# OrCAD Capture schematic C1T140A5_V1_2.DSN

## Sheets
1 00_Log: rev: <V1.2>; note: C1T140A5
2 01_CPU: size A4; title: Telink-Semi; rev: V1.2
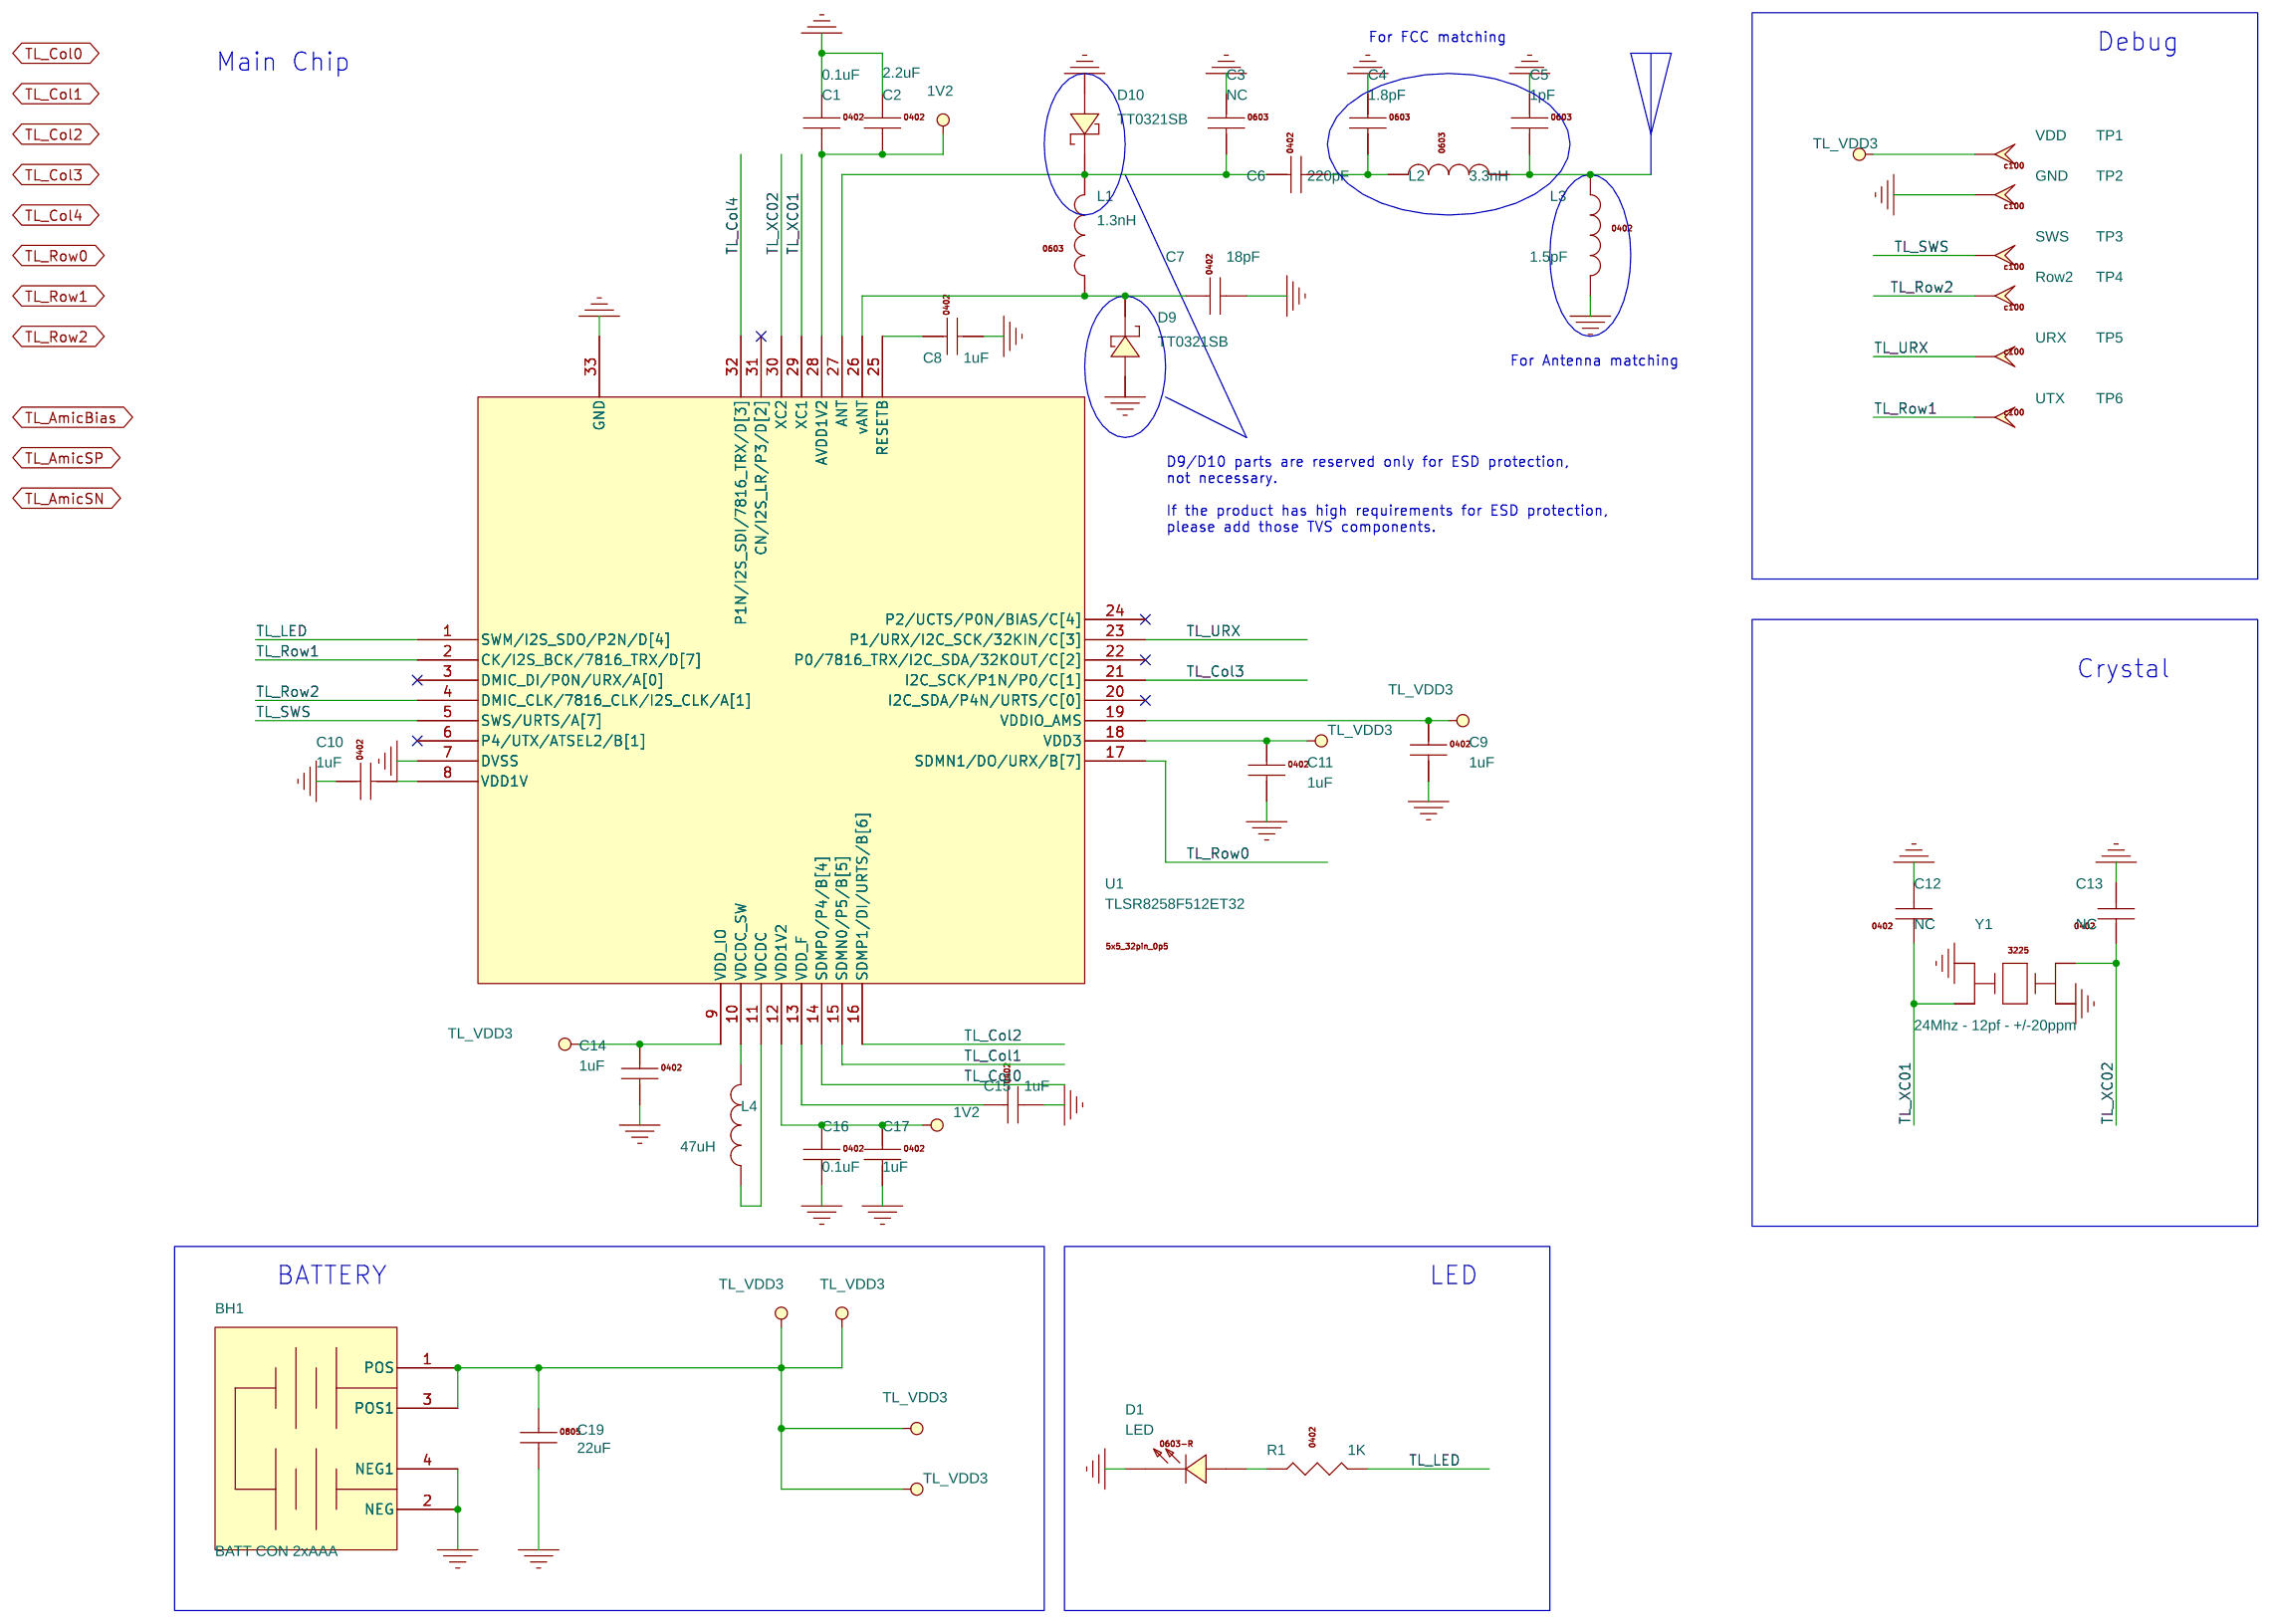
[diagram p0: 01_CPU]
3 02_KEY: size A
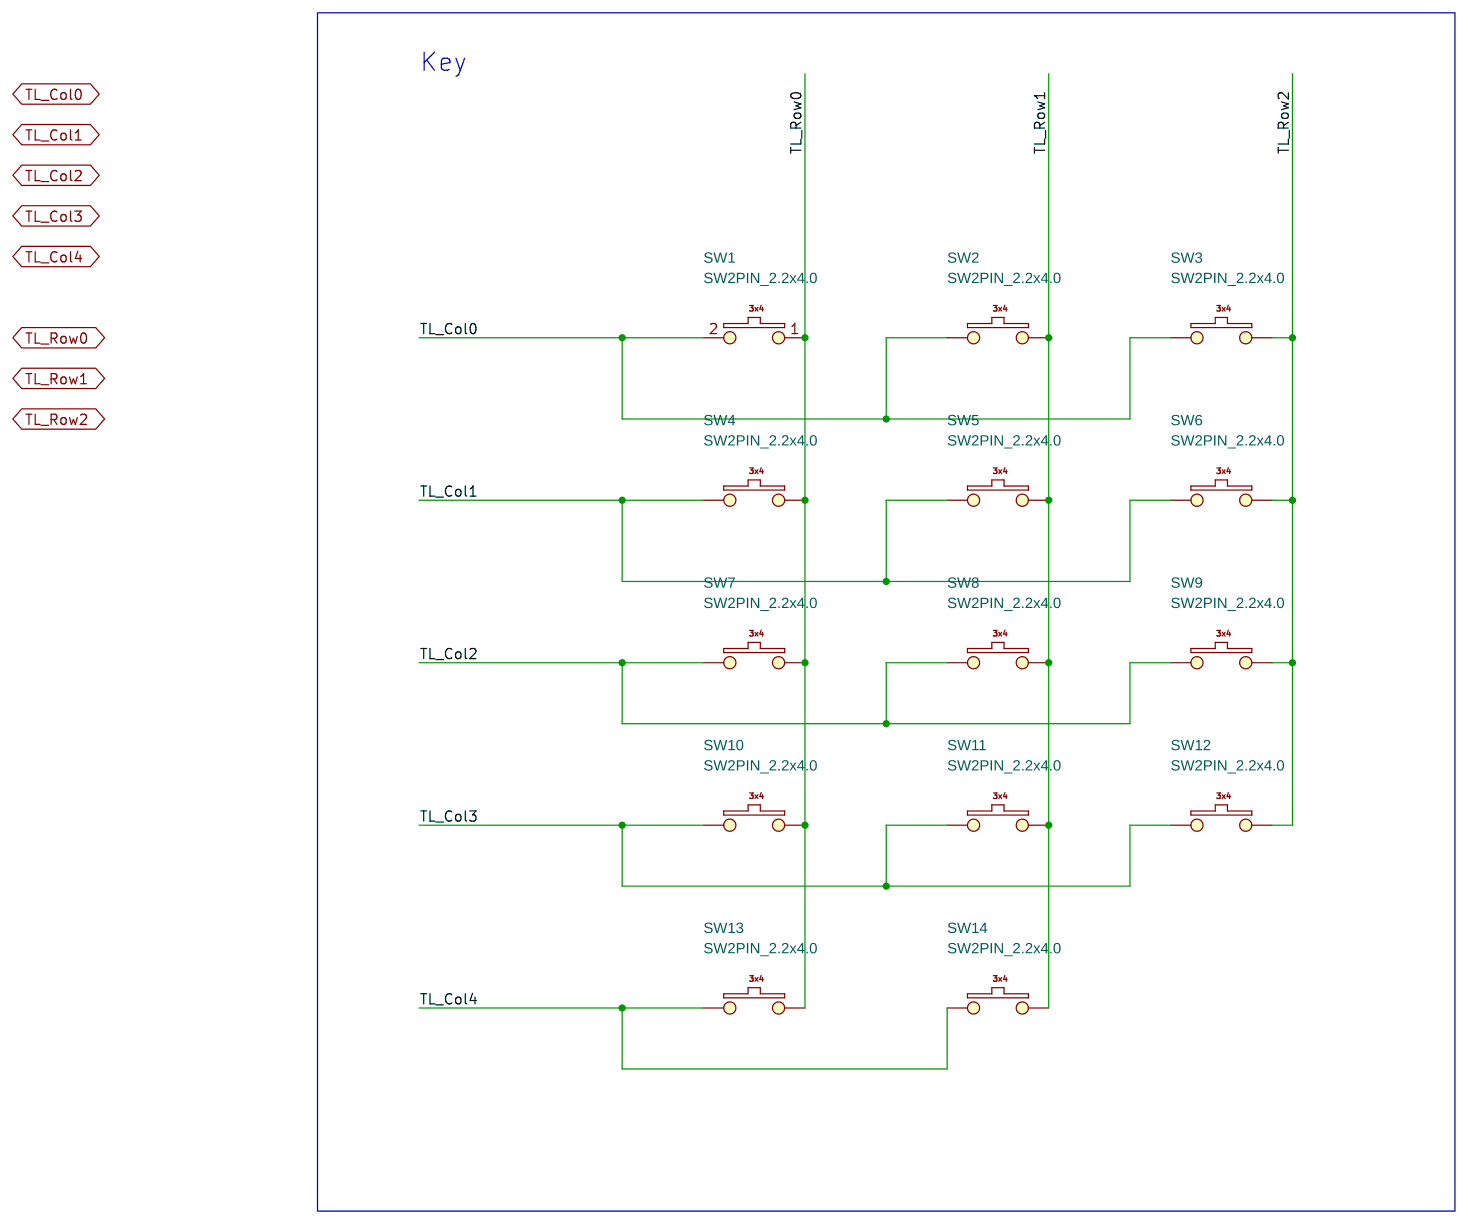
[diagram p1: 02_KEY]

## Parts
sheet 01_CPU
BH1  BATT CON 2xAAA  [bat]
C1  0.1uF  [0402]
C2  2.2uF  [0402]
C3  NC  [0402]
C4  1.8pF  [0402]
C5  1pF  [0402]
C6  220pF  [0402]
C7  18pF  [0402]
C8  1uF  [0402]
C9  1uF  [0402]
C10  1uF  [0402]
C11  1uF  [0402]
C12  NC  [0402]
C13  NC  [0402]
C14  1uF  [0402]
C15  1uF  [0402]
C16  0.1uF  [0402]
C17  1uF  [0402]
C19  22uF  [0805C]
D1  LED  [0603-LED]
D9  TT0321SB  [SOD-123]
D10  TT0321SB  [SOD-123]
L1  1.3nH  [0402]
L2  3.3nH  [0402]
L3  1.5pF  [0402]
L4  47uH  [0805L]
R1  1K  [0402]
TP1  VDD  [tp100]
TP2  GND  [tp100]
TP3  SWS  [tp100]
TP4  Row2  [tp100]
TP5  URX  [tp100]
TP6  UTX  [tp100]
U1  TLSR8258F512ET32  [qfn_5x5_32pin_0p5_2p50x2p50]
Y1  24Mhz - 12pf - +/-20ppm  [osccc250x320x110]
sheet 02_KEY
SW1  SW2PIN_2.2x4.0  [sw_out6_in3_new]
SW2  SW2PIN_2.2x4.0  [sw_out6_in3_new]
SW3  SW2PIN_2.2x4.0  [sw_out6_in3_new]
SW4  SW2PIN_2.2x4.0  [sw_out6_in3_new]
SW5  SW2PIN_2.2x4.0  [sw_out6_in3_new]
SW6  SW2PIN_2.2x4.0  [sw_out6_in3_new]
SW7  SW2PIN_2.2x4.0  [sw_out6_in3_new]
SW8  SW2PIN_2.2x4.0  [sw_out6_in3_new]
SW9  SW2PIN_2.2x4.0  [sw_out6_in3_new]
SW10  SW2PIN_2.2x4.0  [sw_out6_in3_new]
SW11  SW2PIN_2.2x4.0  [sw_out6_in3_new]
SW12  SW2PIN_2.2x4.0  [sw_out6_in3_new]
SW13  SW2PIN_2.2x4.0  [sw_out6_in3_new]
SW14  SW2PIN_2.2x4.0  [sw_out6_in3_new]

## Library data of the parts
BH1 = Chicony_Battery_conn_2xAA_0
C1 C6 C9 C11 C14-C16 = C1005X5R1C104K
C2 = C1005X5R1A225K
C3-C5 = C1608_NC
C7 = C1005C0G1H100D
C8 C10 = C1005X5R1C105K
C12 C13 = C1005_NC
C17 = C1005X5R0J475M
C19 = C2012X5R1A226M
D1 = 0603D_Red
D9 D10 = DIODE_SCHOTTKY_0
L1 L2 = MLK1608_000R
L3 = MLK1005_000R
L4 = IND_0
R1 = RS0402K472JT
TP1-TP6 = TestPad100
U1 = TLSR8258F512ET32
Y1 = OSC_25x32_4pin
SW1 = SW2PIN_8
SW2-SW4 SW6-SW14 = SW2PIN_4
SW5 = SW2PIN_5

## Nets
1V2: C1.2 C2.2 C16.1 C17.1 U1.12(VDD1V2) U1.28(AVDD1V2)
GND: BH1.2(NEG) BH1.4(NEG1) C1.1 C2.1 C3.1 C4.1 C5.1 C7.2 C8.2 C9.2 C10.1 C11.2 C12.2 C13.2 C14.2 C15.2 C16.2 C17.2 C19.2 D1.C(CATHODE) D9.A(ANODE) D10.A(ANODE) L3.2 TP2.1(TP) U1.7(DVSS) U1.33(GND) Y1.2 Y1.4
TL_Col0: U1.14(SDMP0/P4/B[4])
TL_Col0 (page 02_KEY): SW1.2 SW2.2 SW3.2
TL_Col1: U1.15(SDMN0/P5/B[5])
TL_Col1 (page 02_KEY): SW4.2 SW5.2 SW6.2
TL_Col2: U1.16(SDMP1/DI/URTS/B[6])
TL_Col2 (page 02_KEY): SW7.2 SW8.2 SW9.2
TL_Col3: U1.21(I2C_SCK/P1N/P0/C[1])
TL_Col3 (page 02_KEY): SW10.2 SW11.2 SW12.2
TL_Col4: U1.32(P1N/I2S_SDI/7816_TRX/D[3])
TL_Col4 (page 02_KEY): SW13.2 SW14.2
TL_LED: R1.2 U1.1(SWM/I2S_SDO/P2N/D[4])
TL_Row0: U1.17(SDMN1/DO/URX/B[7])
TL_Row0 (page 02_KEY): SW1.1 SW4.1 SW7.1 SW10.1 SW13.1
TL_Row1: TP6.1(TP) U1.2(CK/I2S_BCK/7816_TRX/D[7])
TL_Row1 (page 02_KEY): SW2.1 SW5.1 SW8.1 SW11.1 SW14.1
TL_Row2: TP4.1(TP) U1.4(DMIC_CLK/7816_CLK/I2S_CLK/A[1])
TL_Row2 (page 02_KEY): SW3.1 SW6.1 SW9.1 SW12.1
TL_SWS: TP3.1(TP) U1.5(SWS/URTS/A[7])
TL_URX: TP5.1(TP) U1.23(P1/URX/I2C_SCK/32KIN/C[3])
TL_VDD3: BH1.1(POS) BH1.3(POS1) C9.1 C11.1 C14.1 C19.1 TP1.1(TP) U1.9(VDD_IO) U1.18(VDD3) U1.19(VDDIO_AMS)
TL_XC01: C12.1 U1.29(XC1) Y1.1
TL_XC02: C13.1 U1.30(XC2) Y1.3
N21091201: C7.1 D9.C(CATHODE) L1.1 U1.26(vANT)
N21091209: C3.2 C6.1 D10.C(CATHODE) L1.2 U1.27(ANT)
N21091237: C5.2 L2.2 L3.1
N21091295: C4.2 C6.2 L2.1
N21091335: C8.1 U1.25(RESETB)
N21091386: C10.2 U1.8(VDD1V)
N21091449: L4.1 U1.11(VDCDC)
N21091455: L4.2 U1.10(VDCDC_SW)
N21091487: C15.1 U1.13(VDD_F)
N21100596: D1.A(ANODE) R1.1

Not connected (* = marked no-connect by the designer): U1 3(DMIC_DI/P0N/URX/A[0])* 6(P4/UTX/ATSEL2/B[1])* 20(I2C_SDA/P4N/URTS/C[0])* 22(P0/7816_TRX/I2C_SDA/32KOUT/C[2])* 24(P2/UCTS/P0N/BIAS/C[4])* 31(CN/I2S_LR/P3/D[2])*

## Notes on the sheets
sheet 2
- For FCC matching
- Debug
- Main Chip
- For Antenna matching
- D9/D10 parts are reserved only for ESD protection,
  not necessary.
  If the product has high requirements for ESD protection,
  please add those TVS components.
- Crystal
- BATTERY
- LED
sheet 3
- Key
